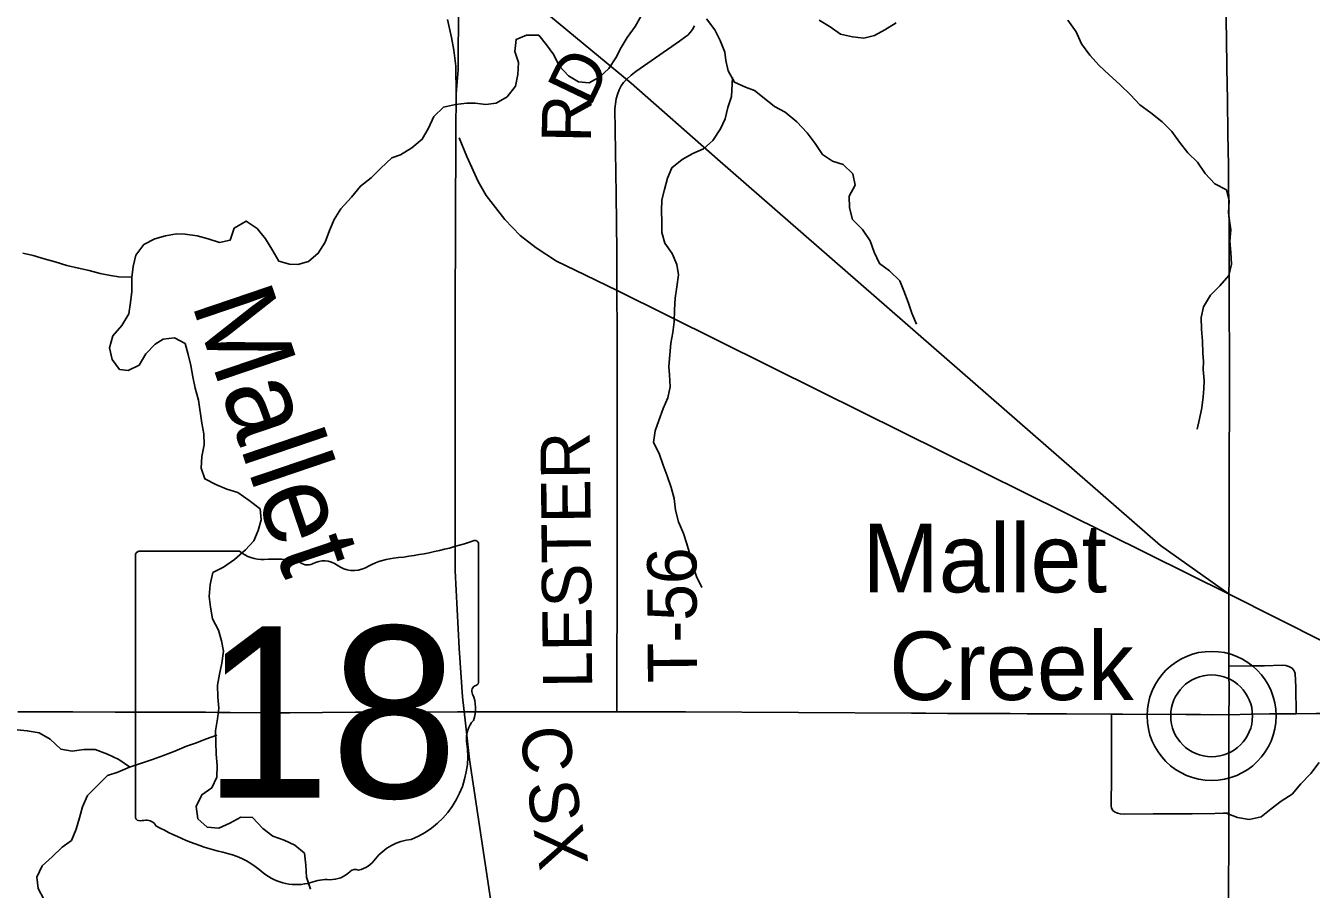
# Model space of a CAD drawing. Extents: x 0 to 34, y 0 to 22.
# Drawn here: x 2.378 to 3.119, y 16.585 to 17.083 of the extents above; entities that cross this region are included whole.
import ezdxf

# ---------------------------------------------------------------- set-up
doc = ezdxf.new("R2010")
doc.units = 0
for name, color, linetype in [('GM_X_County_Road', 7, 'Continuous'), ('GM_X_Minor_River', 7, 'Continuous'), ('GM_X_Minor_River_Text', 7, 'Continuous'), ('GM_X_Rail_Line', 7, 'Continuous'), ('GM_X_Rail_Line_Text', 7, 'Continuous'), ('GM_X_State_Location', 7, 'Continuous'), ('GM_X_State_Route', 7, 'Continuous'), ('GM_X_State_Shield', 7, 'Continuous'), ('GM_X_Township_Road', 7, 'Continuous'), ('GM_X_Township_Road_Text', 7, 'Continuous'), ('GM_X_Unincorporated', 7, 'Continuous'), ('GM_X_Unincorporated_Location', 7, 'Continuous'), ('GM_X_Unincorporated_Text', 7, 'Continuous')]:
    doc.layers.add(name, color=color, linetype=linetype)

msp = doc.modelspace()

# ---------------------------------------------------------------- linework, layer by layer
at = {"layer": 'GM_X_County_Road'}
msp.add_lwpolyline([(3.07167, 16.56846), (3.07176, 16.62869), (3.07186, 16.6855)], dxfattribs=at)
at = {"layer": 'GM_X_Minor_River'}
for points in [[(2.43965, 16.93746), (2.44044, 16.94393), (2.44181, 16.95039), (2.44658, 16.95645), (2.45287, 16.95983), (2.45895, 16.96151), (2.46542, 16.96262), (2.47035, 16.9624), (2.47719, 16.9616), (2.48363, 16.95985), (2.49008, 16.95773), (2.49635, 16.95902), (2.49848, 16.96586), (2.50553, 16.97), (2.51177, 16.96578), (2.51668, 16.95986), (2.52026, 16.95376), (2.52421, 16.94689), (2.53047, 16.94514), (2.53522, 16.94492), (2.54131, 16.94679), (2.54703, 16.95152), (2.55105, 16.95777), (2.55355, 16.9646), (2.55624, 16.97086), (2.56007, 16.97712), (2.56618, 16.98374), (2.57134, 16.99018), (2.57744, 16.9949), (2.58316, 17.00058), (2.58946, 17.00644), (2.59441, 17.00812), (2.60088, 17.01227), (2.60699, 17.01718), (2.61063, 17.02363), (2.6137, 17.03027), (2.61923, 17.03575), (2.62608, 17.03724), (2.63273, 17.03796), (2.63748, 17.03793), (2.64355, 17.03714), (2.64963, 17.03806), (2.65592, 17.04164), (2.66069, 17.04769), (2.66206, 17.05453), (2.66247, 17.06138), (2.66041, 17.06786), (2.66102, 17.0747), (2.66711, 17.07714), (2.67413, 17.0771), (2.67866, 17.07156), (2.68281, 17.06583), (2.68582, 17.05954), (2.6913, 17.0538), (2.69698, 17.05035), (2.70325, 17.04974), (2.70934, 17.05313), (2.71449, 17.05805), (2.71851, 17.06411), (2.72158, 17.06999), (2.72503, 17.07587), (2.72962, 17.08212), (2.73287, 17.088)], [(2.77085, 17.08665), (2.77557, 17.08016), (2.77857, 17.07405), (2.78139, 17.06738), (2.78194, 17.06262), (2.78324, 17.05653), (2.787, 17.05004), (2.79326, 17.04715), (2.79837, 17.04522), (2.80405, 17.04082), (2.80991, 17.03603), (2.81617, 17.03276), (2.82279, 17.02721), (2.82883, 17.0209), (2.83336, 17.01479), (2.8377, 17.00849), (2.84337, 17.00446), (2.84963, 17.00272), (2.85511, 16.99717), (2.85641, 16.9907), (2.85296, 16.98444), (2.85312, 16.97759), (2.85498, 16.97093), (2.86065, 16.96519), (2.86518, 16.9587), (2.86743, 16.95203), (2.87043, 16.94554), (2.8763, 16.94133), (2.88216, 16.93559), (2.8846, 16.92987), (2.88704, 16.9232), (2.88909, 16.91691), (2.89191, 16.91062)], [(2.8358, 17.08591), (2.84205, 17.08207), (2.8481, 17.07785), (2.85493, 17.07629), (2.86139, 17.0755), (2.86766, 17.07698), (2.87356, 17.08019), (2.88004, 17.08433)], [(2.979, 17.08588), (2.9839, 17.07901), (2.98691, 17.07214), (2.99163, 17.06565), (2.9971, 17.05973), (3.00259, 17.05456), (3.0092, 17.04863), (3.01506, 17.0427), (3.02054, 17.03696), (3.02679, 17.03236), (3.03341, 17.02719), (3.03889, 17.02165), (3.04342, 17.01553), (3.04814, 17.00942), (3.05381, 17.00407), (3.05814, 16.99739), (3.06381, 16.99146), (3.07044, 16.988), (3.07193, 16.98171), (3.07171, 16.97487), (3.07225, 16.97011), (3.07299, 16.96497), (3.07238, 16.95851), (3.07292, 16.95185), (3.07327, 16.94519), (3.07191, 16.93873), (3.06656, 16.93267), (3.06122, 16.92737), (3.05719, 16.92055), (3.05583, 16.91447), (3.05599, 16.90762), (3.05672, 16.90077), (3.05687, 16.89392), (3.05723, 16.88917), (3.05701, 16.88441), (3.05755, 16.87813), (3.05734, 16.87338), (3.05694, 16.86863), (3.05634, 16.86235), (3.05498, 16.85608), (3.05362, 16.85)], [(2.76809, 16.75876), (2.76509, 16.76524), (2.76284, 16.77172), (2.76116, 16.77801), (2.75948, 16.78391), (2.75761, 16.79001), (2.75461, 16.79669), (2.75293, 16.80335), (2.7522, 16.8102), (2.75034, 16.81649), (2.74809, 16.82316), (2.74584, 16.82926), (2.74341, 16.83612), (2.74021, 16.84241), (2.74119, 16.84907), (2.74331, 16.85514), (2.74581, 16.86197), (2.7485, 16.86804), (2.74986, 16.8745), (2.74952, 16.88135), (2.74916, 16.88611), (2.74957, 16.89296), (2.75018, 16.89961), (2.75135, 16.90588), (2.75214, 16.91196), (2.75236, 16.91881), (2.75277, 16.92565), (2.75376, 16.93211), (2.75474, 16.93896), (2.75363, 16.94505), (2.751, 16.95134), (2.74685, 16.95726), (2.74498, 16.96335), (2.74501, 16.96963), (2.74485, 16.97591), (2.74508, 16.98218), (2.74662, 16.98826), (2.74837, 16.99472), (2.75087, 17.00079), (2.75678, 17.00551), (2.76287, 17.0089), (2.76915, 17.01172), (2.77449, 17.01645), (2.77889, 17.02327), (2.78158, 17.02896), (2.78313, 17.03542), (2.78525, 17.04187), (2.7857, 17.05282)], [(2.37667, 16.95151), (2.38274, 16.95014), (2.389, 16.94821), (2.39544, 16.94646), (2.40208, 16.94433), (2.40891, 16.94296), (2.41498, 16.9416), (2.42124, 16.93985), (2.42731, 16.93867), (2.43206, 16.93789), (2.43968, 16.9376)], [(2.54255, 16.58486), (2.54031, 16.59188), (2.53978, 16.59873), (2.53905, 16.60558), (2.53357, 16.61037), (2.52731, 16.61325), (2.52087, 16.61538), (2.515, 16.61998), (2.50915, 16.62629), (2.50231, 16.62633), (2.49602, 16.62294), (2.48974, 16.62012), (2.48291, 16.62073), (2.47761, 16.62551), (2.4767, 16.63255), (2.47996, 16.63938), (2.48568, 16.64335), (2.48856, 16.64942), (2.48878, 16.65626), (2.48824, 16.66273), (2.48809, 16.66958), (2.48774, 16.67624), (2.48891, 16.68308), (2.4897, 16.68916), (2.48917, 16.69563), (2.48901, 16.70248), (2.49018, 16.70894), (2.49154, 16.71521), (2.49234, 16.72206), (2.49123, 16.72815), (2.48955, 16.73424), (2.48616, 16.74073), (2.48487, 16.74739), (2.48414, 16.75368), (2.48474, 16.76052), (2.48629, 16.76736), (2.49239, 16.77056), (2.49867, 16.7749), (2.50516, 16.78057), (2.50993, 16.78568), (2.51243, 16.79175), (2.51417, 16.79783), (2.51363, 16.80411), (2.5072, 16.8089), (2.50076, 16.8135), (2.49432, 16.81543), (2.48806, 16.81813), (2.48162, 16.8214), (2.47956, 16.8275), (2.47998, 16.83434), (2.48134, 16.84099), (2.48099, 16.84746), (2.47988, 16.85356), (2.47805, 16.86688), (2.47618, 16.87374), (2.47469, 16.88021), (2.47359, 16.88668), (2.4721, 16.89316), (2.47023, 16.89945), (2.46417, 16.90271), (2.45771, 16.90199), (2.45295, 16.89916), (2.4476, 16.89349), (2.44377, 16.88704), (2.43749, 16.88384), (2.43255, 16.88444), (2.42821, 16.89017), (2.42673, 16.89702), (2.42866, 16.90386), (2.43382, 16.90992), (2.43784, 16.91655), (2.43882, 16.92302), (2.43961, 16.92948), (2.43968, 16.9379)], [(2.43827, 16.65534), (2.43217, 16.65969), (2.42551, 16.66271), (2.41846, 16.66535), (2.412, 16.66533), (2.40517, 16.66455), (2.3987, 16.66567), (2.3926, 16.67135), (2.38612, 16.67494), (2.37927, 16.67625), (2.37357, 16.6768)], [(2.48854, 16.67376), (2.48266, 16.67165), (2.47621, 16.66915), (2.47109, 16.66743), (2.46445, 16.66455), (2.45781, 16.66206), (2.45155, 16.65975), (2.4451, 16.65764), (2.43827, 16.65515), (2.43145, 16.65227), (2.42556, 16.65035), (2.41989, 16.64463), (2.41402, 16.6389), (2.4112, 16.63243), (2.40933, 16.62595), (2.40746, 16.61948), (2.40483, 16.61301), (2.39934, 16.60919), (2.39366, 16.60365), (2.38799, 16.59831), (2.38479, 16.59183), (2.38558, 16.58537), (2.38883, 16.5791)], [(3.0703, 16.6287), (3.07677, 16.62626), (3.08361, 16.62514), (3.09044, 16.62669), (3.09631, 16.63127), (3.10198, 16.63567), (3.10823, 16.63968), (3.11333, 16.6456), (3.119, 16.65152), (3.12391, 16.658)]]:
    msp.add_lwpolyline(points, dxfattribs=at)
at = {"layer": 'GM_X_Rail_Line'}
for points in [[(2.6265, 17.04329), (2.62757, 17.05721), (2.62792, 17.09527), (2.62795, 17.13448), (2.6282, 17.14299), (2.62827, 17.16205), (2.62841, 17.18558), (2.6288, 17.19351), (2.62953, 17.19994), (2.63143, 17.20963), (2.63312, 17.21574), (2.63494, 17.22107), (2.63708, 17.22659), (2.6394, 17.2315), (2.64172, 17.23596), (2.64425, 17.24024), (2.64635, 17.24354), (2.6492, 17.24765), (2.65134, 17.2505), (2.65531, 17.25527), (2.65969, 17.26022), (2.67034, 17.27146)], [(3.07193, 16.75492), (3.03252, 16.78295), (2.77718, 17.00573), (2.72732, 17.0496), (2.67646, 17.09158), (2.65378, 17.11308)], [(2.6265, 17.04329), (2.62628, 17.05939), (2.62515, 17.06858), (2.62389, 17.07575), (2.62145, 17.08626)], [(2.71055, 16.1277), (2.70897, 16.14768), (2.70596, 16.17794), (2.70305, 16.20042), (2.69532, 16.2512), (2.68337, 16.33213), (2.67746, 16.37199), (2.6663, 16.44668), (2.65488, 16.52197), (2.63424, 16.65973), (2.63194, 16.68067), (2.6302, 16.69581), (2.62816, 16.7238), (2.62592, 16.76846), (2.62587, 16.9163), (2.62628, 17.02106), (2.6265, 17.04329)], [(3.07193, 16.75492), (2.83601, 16.87195), (2.71923, 16.93008), (2.69505, 16.94166), (2.68441, 16.94685), (2.67258, 16.9546), (2.66348, 16.96175), (2.65447, 16.97097), (2.64386, 16.98473), (2.63917, 16.99279), (2.63265, 17.00727), (2.62831, 17.01802)], [(4.09477, 16.08516), (4.03987, 16.13182), (3.89227, 16.25797), (3.72331, 16.40276), (3.68279, 16.43758), (3.65598, 16.46005), (3.64908, 16.46516), (3.64049, 16.47094), (3.63155, 16.47631), (3.61517, 16.4846), (3.55809, 16.51291), (3.51008, 16.537), (3.33142, 16.62578), (3.27149, 16.65531), (3.16713, 16.70766), (3.12738, 16.72707), (3.07193, 16.75492)]]:
    msp.add_lwpolyline(points, dxfattribs=at)
at = {"layer": 'GM_X_State_Route'}
msp.add_line((3.07046, 17.07545), (3.07017, 17.09448), dxfattribs=at)
for points in [[(3.0718, 16.71338), (3.07195, 16.80492), (3.07211, 16.83707), (3.07218, 16.8598), (3.07203, 16.95203), (3.07195, 16.96543), (3.07165, 16.99222), (3.07157, 17.00178), (3.07126, 17.02054), (3.07103, 17.03967), (3.07073, 17.05842), (3.07046, 17.07545)], [(3.07186, 16.6855), (3.07194, 16.69594), (3.0718, 16.71338)], [(2.37385, 16.68716), (2.39409, 16.68711), (2.40565, 16.68708), (2.43005, 16.68701), (2.45188, 16.68695), (2.48196, 16.68686), (2.48997, 16.68682), (2.49632, 16.68678), (2.52398, 16.68662), (2.53061, 16.68659), (2.54943, 16.68676), (2.56842, 16.68686), (2.59454, 16.68701), (2.62731, 16.68719), (2.63135, 16.68721), (2.71907, 16.68721), (2.72914, 16.68719)], [(2.72914, 16.68719), (2.74476, 16.68716), (2.75868, 16.68708), (2.88893, 16.68634)], [(2.88893, 16.68634), (2.88993, 16.68634), (2.89725, 16.6863), (2.90961, 16.68625), (2.92166, 16.6862), (2.93395, 16.68615), (2.94577, 16.6861), (2.95564, 16.68607), (2.97283, 16.686), (2.97817, 16.68596), (3.00422, 16.68583), (3.01057, 16.6858), (3.04696, 16.68562), (3.0554, 16.68558), (3.07186, 16.6855)], [(3.07186, 16.6855), (3.08468, 16.6858), (3.09524, 16.68589), (3.10153, 16.68595), (3.11061, 16.68606)], [(3.11061, 16.68606), (3.12211, 16.68613), (3.13363, 16.68623), (3.14176, 16.6863), (3.18056, 16.68612), (3.18268, 16.68584), (3.18766, 16.68375)]]:
    msp.add_lwpolyline(points, dxfattribs=at)
at = {"layer": 'GM_X_State_Shield'}
for p, q in [((2.63944, 16.70488), (2.63944, 16.78339)), ((2.44169, 16.77709), (2.44169, 16.627)), ((2.50155, 16.77968), (2.44364, 16.77968)), ((2.63942, 16.7049), (2.63944, 16.70488))]:
    msp.add_line(p, q, dxfattribs=at)
for centre, radius, start, end in [((2.569, 16.9843), 0.20971, 275.84447, 288.90645), ((2.63725, 16.78372), 0.0022, 351.86209, 97.738), ((2.44396, 16.77741), 0.00229, 98.1301, 188.1301), ((2.51534, 16.7971), 0.02222, 231.61951, 271.11188), ((2.52271, 16.69541), 0.07977, 80.48669, 94.98827), ((2.59575, 16.73383), 0.04219, 97.34618, 120.76885), ((2.54082, 16.77819), 0.00641, 219.79206, 297.10237), ((2.55023, 16.76084), 0.01333, 54.46668, 119.14113), ((2.56744, 16.78464), 0.01603, 233.85621, 294.82819), ((2.63894, 16.69912), 0.00341, 107.94398, 210.33697), ((2.6371, 16.70458), 0.00236, 289.60381, 7.73413), ((2.61726, 16.68919), 0.02045, 340.03296, 23.64957), ((2.64733, 16.67202), 0.01488, 136.8065, 186.92959), ((2.58075, 16.66204), 0.05245, 292.30889, 8.98584), ((2.44398, 16.62667), 0.00231, 171.95839, 258.30661), ((2.44433, 16.64203), 0.01764, 267.33899, 280.60386), ((2.44794, 16.61834), 0.00636, 29.74838, 93.27175), ((2.52823, 16.75319), 0.15144, 240.41292, 257.1985), ((2.60287, 16.58486), 0.02873, 94.40312, 142.57675), ((2.48308, 16.55957), 0.04738, 47.18416, 75.83597), ((2.56647, 16.61246), 0.01695, 282.87319, 323.27711), ((2.53433, 16.6176), 0.03007, 230.70037, 286.29184), ((2.5517, 16.56571), 0.02471, 85.69512, 111.20995), ((2.5539, 16.60636), 0.01602, 268.77702, 315.54927), ((2.56839, 16.59182), 0.00451, 65.75173, 132.64842)]:
    msp.add_arc(centre, radius, start, end, dxfattribs=at)
at = {"layer": 'GM_X_Township_Road'}
for points in [[(2.71907, 16.68721), (2.71937, 16.77766), (2.71922, 16.90229), (2.71914, 16.93316), (2.71907, 16.95222), (2.71876, 16.98556), (2.71802, 17.03475), (2.71832, 17.03769), (2.71877, 17.0404), (2.71945, 17.04304), (2.72042, 17.04575), (2.72163, 17.04793), (2.72299, 17.04981), (2.72479, 17.05177), (2.72743, 17.05418), (2.7301, 17.05617), (2.75529, 17.07376), (2.75891, 17.07632), (2.75995, 17.07722), (2.76132, 17.07866), (2.76275, 17.08054), (2.7638, 17.08265)], [(3.0718, 16.71338), (3.08481, 16.71361), (3.09231, 16.71369), (3.10257, 16.714), (3.10464, 16.71384), (3.10632, 16.71331), (3.10724, 16.71285), (3.10831, 16.71223)], [(3.11061, 16.68606), (3.11038, 16.70137), (3.11007, 16.70917), (3.10946, 16.7107), (3.10892, 16.71154), (3.10831, 16.71223)], [(3.00502, 16.63025), (3.00449, 16.63087), (3.00423, 16.63174), (3.00406, 16.63279), (3.00423, 16.65024), (3.00428, 16.66699), (3.00422, 16.68583)], [(3.00502, 16.63025), (3.00598, 16.62956), (3.00763, 16.62877), (3.00929, 16.62834), (3.01147, 16.62816), (3.02814, 16.62825), (3.05066, 16.62842), (3.06375, 16.62851), (3.06862, 16.62865), (3.07176, 16.62869)]]:
    msp.add_lwpolyline(points, dxfattribs=at)
at = {"layer": 'GM_X_Unincorporated'}
for radius in [0.0372, 0.02358]:
    msp.add_circle((3.0619, 16.6848), radius, dxfattribs=at)
at = {"layer": 'GM_X_Unincorporated_Location'}
msp.add_line((3.0619, 16.6848), (3.0619, 16.6848), dxfattribs=at)

# ---------------------------------------------------------------- texts
at = {"layer": 'GM_X_Minor_River_Text'}
msp.add_text('Mallet', height=0.04737, rotation=288.75759, dxfattribs=at).set_placement((2.47376, 16.92269))
at = {"layer": 'GM_X_Rail_Line_Text'}
for s, rotation, p in [('C', 277.08289, (2.66317, 16.67724)), ('S', 278.58429, (2.66712, 16.64557)), ('X', 278.75861, (2.671, 16.6199))]:
    msp.add_text(s, height=0.02831, rotation=rotation, dxfattribs=at).set_placement(p)
at = {"layer": 'GM_X_State_Location'}
for s, p in [('s', (2.53914, 16.67391)), ('r', (2.53913, 16.67391))]:
    msp.add_text(s, height=0.0000947, dxfattribs=at).set_placement(p)
msp.add_text('18', height=0.0000947, rotation=0.00001, dxfattribs=at).set_placement((2.51529, 16.66702))
at = {"layer": 'GM_X_State_Shield'}
msp.add_text('18', height=0.098877, dxfattribs=at).set_placement((2.48049, 16.63759))
at = {"layer": 'GM_X_Township_Road_Text'}
for s, height, rotation, p in [('D', 0.02841, 64.39616, (2.70383, 17.03529)), ('R', 0.02841, 88.89926, (2.70412, 17.01507)), ('LESTER', 0.028409, 90.56141, (2.70494, 16.70093)), ('T-56', 0.028409, 90.35349, (2.76543, 16.70385))]:
    msp.add_text(s, height=height, rotation=rotation, dxfattribs=at).set_placement(p)
at = {"layer": 'GM_X_Unincorporated_Text'}
for s, p in [('Mallet', (2.8607, 16.75602)), ('Creek', (2.87612, 16.69394))]:
    msp.add_text(s, height=0.039489, rotation=0.00001, dxfattribs=at).set_placement(p)

doc.saveas('drawing.dxf')
